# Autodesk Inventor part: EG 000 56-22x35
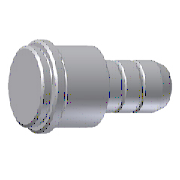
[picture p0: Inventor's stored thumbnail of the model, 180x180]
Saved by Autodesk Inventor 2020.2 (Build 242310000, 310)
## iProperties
Manager: www.cadconsulting.pl
Company: Fabian Stasiak CAD Consulting
IsCustomPart: 0
Created: 2014-02
Part Number: EG 000 56-22x35
Material: DIN 1.7131
Description: Leader Pins
Document SubType Name: Modeling
Designer: F.Stasiak
Standard Revision: 1
Manufacturer: DME
Language: pl-PL
Size Designation: 56-22x35
Categories: <MemberInstance><Categories><Category DisplayName="Forma wtryskowa" InternalName="349578f2-f4d4-4954-8c09-8e99297a61c0" Mnemonic="MOLD"><Category DisplayName="K
Mass: 4.19143 g
Surface Area: 17.8137 cm^2
Volume: 4.19143 cm^3
Density: 7.85 g/cm^3
Appearance: Stal
Catalog Web Link: www.expertbooks.pl
Author: F.Stasiak
Subject: Zbiór ćwiczeń. Autodesk Inventor 2020. Kurs Professional
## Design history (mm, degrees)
sketch "Sketch1"
  geometry: L1 (0, -42.393)-(0, 14.066) reference; L2 (0, 15)-(15, 15); L3 (15, 15)-(15, 7); L4 (14.5, 6)-(17.5, 6); L5 (17.5, 6)-(17.5, 0); L6 (17.5, 0)-(14.5, 0); L7 (15, -1)-(15, -48); L8 (15, -48)-(15, -48); L9 (15, -48)-(15, -50); L10 (15, -50)-(11, -50); L11 (11, -78)-(9.522, -83.518); L12 (7.59, -85)-(0, -85); L13 (11, -50)-(11, -78); L14 (14.5, 0)-(14.5, -1); L15 (14.5, -1)-(15, -1); L16 (14.5, 7)-(15, 7); L17 (14.5, 7)-(14.5, 6); L18 (0, 15)-(0, -85); A1 r 2 centre (7.59, -83) between (7.59, -85) and (9.522, -83.518); 1 further point
  constraints: 38 end point, 7 perpendicular, 6 parallel, 2 collinear, 2 point on circle, 2 point on line, 2 tangent, 2 vertical alignment, 1 centre point, 1 horizontal alignment
  dimensions: "d73" = 6 distance between parallel lines of L6 L4 (derived); "d74" = 9 distance between parallel lines of L2 L4 (derived); "d75" = 56 distance between parallel lines of L10 L4 (derived); "d76" = 2 distance between parallel lines of L10 L8; "d77" = 35 diameter of L5 L1 (derived); "d78" = 35 distance between parallel lines of L12 L10 (derived); "d79" = 30 diameter of L3 L1 (derived); "d89" = 7 distance from line of L12 L11.start (derived); "d92" = 22 diameter of L13 L1 (derived); "d94" = 30 diameter of L7 L1 (derived); "d97" = 2 radius of A1; "d110" = 0.5 distance between parallel lines of L7 L14; "d111" = 1 distance from line of L6.end L15; "d112" = 0.5 distance between parallel lines of L3 L17; "d113" = 1 distance between parallel lines of L4 L16; "d114" = 30 diameter of L9 L18 (derived); "d120" = 15 deg angle of L13 L11
revolve "Revolution1" sketch "Sketch1" stored, may be unused: angle "d100" = 90 deg
chamfer "Chamfer1" distance "d106" = 0.5; stored, may be unused: second distance "d107" = 2, angle "d108" = 45 deg
fillet "Fillet1" dims "d109" = 0.3
sketch "Sketch2"
  geometry: L1 (-7.59, -85)-(7.59, -85) reference; L2 (0, -40.8)-(0, 6.8) reference; C1 r 1.375 at (11.275, -59.333); C2 r 1.375 at (11.275, -68.667); 1 further point
  constraints: 2 centre point, 1 equal radius, 1 vertical alignment
  dimensions: "d121" = 2.75 diameter of C1 (derived); "d122" = 16.33333 distance from line of L1 C2.centre (derived); "d123" = 25.66667 distance from line of L1 C1.centre (derived); "d129" = 22.55 diameter of C1.centre L2 (derived)
revolve "Revolution2" sketch "Sketch2" stored, may be unused: angle "d126" = 90 deg
body "Solid1"
other parameters: "d3" = 35 [user parameter], "l2" = 9 [user parameter], "l1" = 6 [user parameter], "A_" = 56 [user parameter], "B" = 35 [user parameter], "d1" = 22 [user parameter; used in 1 equation term], "d43" = 22 (= d1), "d91" = 8, "d101" = 0, "d103" = 0, "ob" = 7 [user parameter], "B1" = 16.33333 [user parameter], "G1" = 25.66667 [user parameter], "d128" = 0, "L_" = 91 [user parameter]
